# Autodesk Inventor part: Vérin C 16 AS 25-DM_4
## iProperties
Shininess: 20.0
Angle Display Precision: 2
Document Length Units: 11269
Document Angle Units: 11279
Document Time Units: 11290
Document Mass Units: 11283
Document Length Units Precision: 3
Document Angle Units Precision: 2
Created: 2002-02
Part Number: Vérin C 16 AS 25-DM_4
Material: Par défaut
Document SubType Name: Modélisation
Designer: Administrateur
Density: 0.0
Volumn: 0.0
Area: 0.0
PropertySet Name: Model Information
Control State: 0
Master: False
Checked Out: False
Author: Administrateur
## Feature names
1. Base1
